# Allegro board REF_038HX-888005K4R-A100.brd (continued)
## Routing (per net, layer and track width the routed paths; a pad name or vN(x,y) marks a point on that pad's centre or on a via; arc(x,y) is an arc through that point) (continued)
D10901: length 268.7
  TOP w0.203: v2(221.27,240.33) 220.98,240.03 220.98,238.29 219.28,236.6 219.28,233.36 214.12,228.2 SITE2.91
  L05_SIGNAL w0.135: 254.73,254.67 254.73,254.08 255.08,253.72 256.42,253.72 258.68,255.99 258.68,309.03 279.04,329.39 279.04,335.94 278.28,336.71 275.56,336.71 274.13,335.27 274.13,334.28
  L05_SIGNAL w0.145: 274.13,334.28 274.49,333.92 276.84,333.92 277.13,333.63 D109.01 ; v2(255.45,254.94) 255,254.94 254.73,254.67
  L22_SIGNAL w0.135: 220.91,240.7 220.91,243.99 221.98,245.06 222.17,245.06 222.35,244.89 222.54,244.89 222.73,245.08 222.73,245.27 222.56,245.45 222.56,245.64 223.76,246.84 224.32,246.84 224.68,246.47 224.68,241.14 225.2,240.62 226.11,240.62 226.69,241.2 226.69,246.32 227.2,246.84 230.93,246.84 231.4,246.37 231.4,236.52 232.05,235.87 233.27,235.87 233.88,236.48 233.88,246.63 234.24,247 235.01,247 235.34,246.66 235.34,236.22 235.87,235.69 237.56,235.69 238.04,236.16 238.04,246.22 238.65,246.84 251.13,246.84 251.68,246.29 251.68,244.05 251.11,243.48 242.16,243.48 241.34,242.66 241.34,239.22 242.07,238.49 260.03,238.49 260.95,239.41 260.95,240.66 254.73,246.88 254.73,254.67
  L22_SIGNAL w0.145: v2(255.45,254.94) 255,254.94 254.73,254.67 ; v2(221.27,240.33) 220.91,240.7
D10902: length 268.7
  TOP w0.203: v2(231.73,227.81) 231.44,228.1 224.66,228.1 219.39,222.83 SITE2.87
  L03_SIGNAL w0.135: 254.73,288.23 254.73,289.31 249.72,294.32 249.72,303.52 273.03,326.84 273.03,328.64
  L03_SIGNAL w0.145: 254.73,288.23 255,287.96 v2(255.45,287.96) ; 273.03,328.64 D109.02
  L22_SIGNAL w0.135: 254.73,287.69 254.73,286.42 254.22,285.91 253.08,285.91 251.91,287.08 251.91,301.72 257.33,307.14 269.91,307.14 272.49,304.56 272.49,294.81 262.47,284.79 262.47,244.51 267.05,239.93 267.05,216.1 266.52,215.56 262.59,215.56 261.97,216.18 261.97,235.46 261.52,235.91 241.64,235.91 233.91,228.17 232.1,228.17
  L22_SIGNAL w0.145: v2(231.73,227.81) 232.1,228.17 ; v2(255.45,287.96) 255,287.96 254.73,287.69
D10903: length 268.7
  TOP w0.203: v2(220.13,240.33) 220.43,240.03 220.43,238.52 218.73,236.83 218.73,233.59 213.72,228.57 SITE2.92
  L05_SIGNAL w0.135: 254.32,254.67 254.32,253.91 254.91,253.32 256.58,253.32 259.09,255.82 259.09,308.86 279.45,329.22 279.45,336.11 278.45,337.12 275.39,337.12 273.72,335.44 273.72,334.41
  L05_SIGNAL w0.145: v2(253.59,254.94) 254.05,254.94 254.32,254.67 ; D109.03 273.72,334.41
  L22_SIGNAL w0.135: 220.5,240.7 220.5,244.16 223.59,247.24 224.49,247.24 225.09,246.64 225.09,241.31 225.37,241.03 225.94,241.03 226.28,241.37 226.28,246.49 227.03,247.24 231.1,247.24 231.8,246.54 231.8,236.69 232.22,236.27 233.1,236.27 233.47,236.65 233.47,246.8 234.07,247.4 235.18,247.4 235.75,246.83 235.75,236.39 236.04,236.1 237.39,236.1 237.63,236.33 237.63,246.39 238.48,247.24 251.3,247.24 252.09,246.45 252.09,243.88 251.28,243.07 242.33,243.07 241.75,242.49 241.75,239.39 242.23,238.9 259.86,238.9 260.54,239.58 260.54,240.49 254.32,246.71 254.32,254.67
  L22_SIGNAL w0.145: v2(253.59,254.94) 254.05,254.94 254.32,254.67 ; v2(220.13,240.33) 220.5,240.7
D10904: length 268.7
  TOP w0.203: v2(231.73,228.95) 231.44,228.65 224.43,228.65 219.01,223.23 SITE2.88
  L03_SIGNAL w0.135: 272.62,328.68 272.62,327.01 249.31,303.69 249.31,294.15 254.32,289.14 254.32,288.23
  L03_SIGNAL w0.145: D109.04 269.31,330.2 269.04,329.93 269.04,329.2 269.21,329.03 272.27,329.03 272.62,328.68 ; 254.32,288.23 254.05,287.96 v2(253.59,287.96)
  L22_SIGNAL w0.135: 232.1,228.58 233.74,228.58 234.99,229.83 234.99,230.02 234.93,230.08 234.93,230.27 235.12,230.46 235.31,230.46 235.37,230.4 235.56,230.4 241.47,236.32 261.69,236.32 262.38,235.63 262.38,216.35 262.76,215.97 266.35,215.97 266.64,216.27 266.64,239.76 262.06,244.34 262.06,284.96 272.08,294.98 272.08,304.4 269.74,306.73 257.5,306.73 252.31,301.55 252.31,287.25 253.25,286.32 254.05,286.32 254.32,286.59 254.32,287.69
  L22_SIGNAL w0.145: v2(231.73,228.95) 232.1,228.58 ; v2(253.59,287.96) 254.05,287.96 254.32,287.69
D10905: length 268.7
  TOP w0.203: SITE2.75 226.04,218.03 226.11,217.96 234.48,217.96 v2(234.78,217.66)
  L05_SIGNAL w0.135: 269.97,265.48 269.97,264.93 269.27,264.23 267.28,264.23 264.55,266.96 264.55,310.56 282.37,328.38 282.37,338.89 281.11,340.14 267.5,340.14 265.34,337.99 265.34,334.37
  L05_SIGNAL w0.145: v2(270.69,265.75) 270.24,265.75 269.97,265.48 ; D109.05 265.34,334.37
  L20_SIGNAL w0.135: 269.97,265.48 269.97,263.55 270.83,262.69 272.56,262.69 272.93,263.06 272.93,275.29 274.4,276.76 283.7,276.76 284.95,275.5 284.95,221.53 281.45,218.03 239.29,218.03 239.16,217.89 239.16,217.62 239.02,217.48 238.75,217.48 238.62,217.62 238.62,217.89 238.48,218.03 238.22,218.03 238.08,217.89 238.08,217.62 237.95,217.48 237.68,217.48 237.54,217.62 237.54,217.89 237.41,218.03 237.14,218.03 237,217.89 237,217.62 236.87,217.48 236.6,217.48 236.47,217.62 236.47,217.89 236.33,218.03 235.15,218.03
  L20_SIGNAL w0.145: v2(270.69,265.75) 270.24,265.75 269.97,265.48 ; v2(234.78,217.66) 235.15,218.03
D10906: length 268.7
  TOP w0.203: v2(215.49,243.07) 215.19,242.77 215.19,238.91 214.32,238.04 214.32,234.11 211.32,231.12 SITE2.98
  L03_SIGNAL w0.135: 254.73,282.53 254.73,283.45 245.97,292.21 245.97,304.79 262.45,321.27 262.45,328.22
  L03_SIGNAL w0.145: v2(255.45,282.26) 255,282.26 254.73,282.53 ; 262.45,328.22 D109.06
  L20_SIGNAL w0.135: 254.73,281.99 254.73,278.49 256.76,276.45 256.76,274.95 255.28,273.47 253.83,273.47 252.13,275.16 252.13,278.94 251.75,279.32 250.49,279.32 250.07,278.9 250.07,274.07 251.76,272.38 251.76,266.35 243.29,257.88 235.32,257.88 234.32,256.88 234.32,253.81 236.32,251.81 238.71,251.81 241.25,249.28 259.82,249.28 260.42,248.69 260.42,246.45 259.95,245.99 246.32,245.99 245.64,245.31 245.64,243.82 246.32,243.14 263.81,243.14 264.53,242.42 264.53,239.46 264.03,238.96 247.09,238.96 241.37,244.68 241.37,246.4 240.72,247.05 237.32,247.05 232.67,251.69 220.68,251.69 216.37,247.38 216.37,247.19 216.54,247.01 216.54,246.82 216.35,246.63 216.16,246.63 215.99,246.81 215.79,246.81 215.12,246.13 215.12,243.43
  L20_SIGNAL w0.145: v2(255.45,282.26) 255,282.26 254.73,281.99 ; v2(215.49,243.07) 215.12,243.43
D10907: length 268.7
  TOP w0.203: v2(234.78,218.8) 234.48,218.5 226.15,218.5 226.08,218.43 SITE2.76
  L05_SIGNAL w0.135: 264.93,334.4 264.93,338.16 267.33,340.55 281.28,340.55 282.78,339.06 282.78,328.21 264.96,310.39 264.96,267.13 267.45,264.64 269.1,264.64 269.56,265.1 269.56,265.48
  L05_SIGNAL w0.145: 269.56,265.48 269.29,265.75 v2(268.83,265.75) ; D109.07 261.52,332.74 261.34,332.92 261.34,333.8 261.68,334.14 264.67,334.14 264.93,334.4
  L20_SIGNAL w0.135: 269.56,265.48 269.56,263.38 270.66,262.28 272.73,262.28 273.34,262.89 273.34,275.12 274.57,276.35 283.53,276.35 284.55,275.33 284.55,221.7 281.28,218.43 235.15,218.43
  L20_SIGNAL w0.145: v2(234.78,218.8) 235.15,218.43 ; 269.56,265.48 269.29,265.75 v2(268.83,265.75)
D10908: length 268.7
  TOP w0.203: v2(214.34,243.07) 214.64,242.77 214.64,239.13 213.77,238.26 213.77,234.34 210.92,231.49 SITE2.99
  L03_SIGNAL w0.135: 254.32,282.53 254.32,283.28 245.57,292.04 245.57,304.96 262.04,321.44 262.04,328.33
  L03_SIGNAL w0.145: 262.04,328.33 261.35,329.03 260.52,329.03 D109.08 ; v2(253.59,282.26) 254.05,282.26 254.32,282.53
  L20_SIGNAL w0.135: 254.32,281.99 254.32,278.32 256.36,276.28 256.36,275.12 255.11,273.88 254,273.88 252.54,275.33 252.54,279.11 251.92,279.73 250.32,279.73 249.66,279.07 249.66,273.9 251.35,272.22 251.35,266.52 243.12,258.29 235.15,258.29 233.91,257.05 233.91,253.64 236.15,251.41 238.54,251.41 241.08,248.87 259.65,248.87 260.01,248.52 260.01,246.62 259.78,246.4 246.15,246.4 245.24,245.48 245.24,243.65 246.15,242.73 263.64,242.73 264.12,242.25 264.12,239.63 263.86,239.37 247.26,239.37 241.78,244.85 241.78,246.57 240.89,247.46 237.49,247.46 232.84,252.1 220.51,252.1 214.71,246.3 214.71,243.43
  L20_SIGNAL w0.145: v2(253.59,282.26) 254.05,282.26 254.32,281.99 ; v2(214.34,243.07) 214.71,243.43
D10909: length 268.7
  TOP w0.203: v2(219.34,243.07) 219.05,242.77 219.05,238.44 217.8,237.19 217.8,233.61 213.32,229.13 SITE2.93
  L05_SIGNAL w0.135: 255.37,334.17 255.37,336.32 251.52,340.17 234.61,340.17 231.41,336.97 231.41,315.42 248.15,298.68 248.15,267.87 251.93,264.09 254.08,264.09 254.73,264.74 254.73,265.48
  L05_SIGNAL w0.145: v2(255.45,265.75) 255,265.75 254.73,265.48 ; D109.09 255.37,334.17
  L20_SIGNAL w0.135: 254.73,265.48 254.73,264.32 256.51,262.54 256.51,256.8 255.91,256.2 253.73,256.2 253.09,256.83 253.09,260.7 252.86,260.93 250.35,260.93 250.07,260.66 250.07,256.09 249.06,255.08 242.56,255.08 241.92,254.43 241.92,253.03 242.51,252.43 259.44,252.43 263.06,248.81 265.3,248.81 266.74,247.37 266.74,236.62 265.87,235.75 243.7,235.75 230.42,249.03 222.86,249.03 220.34,246.51 220.34,246.32 220.51,246.14 220.51,245.95 220.32,245.76 220.13,245.76 219.96,245.94 219.77,245.94 218.98,245.15 218.98,243.43
  L20_SIGNAL w0.145: 254.73,265.48 255,265.75 v2(255.45,265.75) ; v2(219.34,243.07) 218.98,243.43
D10910: length 268.7
  TOP w0.203: SITE2.122 201.72,231.79 200.33,233.17 200.33,240.03 v2(200.63,240.33)
  L03_SIGNAL w0.135: 252.22,328.16 252.22,317.35 225.72,290.84 225.72,285.24 218.63,278.16 213.65,278.16 208.74,273.26 208.74,271.72
  L03_SIGNAL w0.145: 252.22,328.16 D109.10 ; v2(209.47,271.45) 209.01,271.45 208.74,271.72
  L22_SIGNAL w0.135: 208.74,271.18 208.74,270.27 209.14,269.87 209.73,269.87 210.7,270.84 210.7,279.3 216.13,284.73 216.13,314 217.09,314.96 219.2,314.96 220.2,313.96 220.2,303.87 220.59,303.47 221.92,303.47 222.49,304.04 222.49,314.02 223.42,314.96 225.27,314.96 226.17,314.05 226.17,268.72 225.1,267.65 217.05,267.65 211.4,262 211.4,254.09 208.2,250.9 206.65,250.9 200.27,244.51 200.27,242.39 200.4,242.25 200.65,242.25 200.78,242.12 200.78,241.85 200.65,241.71 200.4,241.71 200.27,241.58 200.27,240.7
  L22_SIGNAL w0.145: v2(200.63,240.33) 200.27,240.7 ; v2(209.47,271.45) 209.01,271.45 208.74,271.18
D10911: length 268.7
  TOP w0.203: SITE2.94 212.92,229.51 217.25,233.84 217.25,237.42 218.5,238.66 218.5,242.77 v2(218.2,243.07)
  L05_SIGNAL w0.135: 254.32,265.48 254.32,264.91 253.91,264.5 252.1,264.5 248.55,268.04 248.55,298.85 231.82,315.59 231.82,336.8 234.78,339.76 251.35,339.76 254.97,336.15 254.97,334.26
  L05_SIGNAL w0.145: 254.32,265.48 254.05,265.75 v2(253.59,265.75) ; 254.97,334.26 254.61,333.9 251.36,333.9 251.06,333.6 251.06,332.93 251.25,332.74 D109.11
  L20_SIGNAL w0.135: 218.57,243.43 218.57,245.32 222.69,249.44 230.59,249.44 243.87,236.16 265.7,236.16 266.33,236.79 266.33,247.2 265.13,248.4 262.89,248.4 259.27,252.02 242.34,252.02 241.51,252.86 241.51,254.6 242.39,255.49 248.89,255.49 249.67,256.26 249.67,260.82 250.18,261.34 253.03,261.34 253.5,260.87 253.5,257 253.9,256.61 255.74,256.61 256.1,256.97 256.1,262.37 254.32,264.15 254.32,265.48
  L20_SIGNAL w0.145: v2(218.2,243.07) 218.57,243.43 ; 254.32,265.48 254.05,265.75 v2(253.59,265.75)
D10912: length 268.7
  TOP w0.203: v2(199.49,240.33) 199.79,240.03 199.79,232.94 201.32,231.41 SITE2.123
  L03_SIGNAL w0.135: 251.82,328.28 251.82,317.52 225.31,291.01 225.31,285.41 218.46,278.57 213.48,278.57 208.33,273.43 208.33,271.72
  L03_SIGNAL w0.145: 208.33,271.72 208.07,271.45 v2(207.61,271.45) ; D109.12 250.36,329.03 251.07,329.03 251.82,328.28
  L22_SIGNAL w0.135: 208.33,271.18 208.33,270.1 208.97,269.46 209.9,269.46 211.11,270.67 211.11,279.13 216.54,284.56 216.54,313.83 217.26,314.55 219.03,314.55 219.79,313.79 219.79,303.7 220.42,303.06 222.09,303.06 222.89,303.87 222.89,313.85 223.59,314.55 225.1,314.55 225.76,313.88 225.76,268.89 224.93,268.06 216.88,268.06 210.99,262.17 210.99,254.26 208.03,251.31 206.48,251.31 199.86,244.68 199.86,240.7
  L22_SIGNAL w0.145: v2(207.61,271.45) 208.07,271.45 208.33,271.18 ; v2(199.49,240.33) 199.86,240.7
D10913: length 268.7
  TOP w0.203: SITE2.95 212.52,229.94 216.33,233.75 216.33,238.1 217.12,238.88 217.12,240.03 v2(217.41,240.33)
  L05_SIGNAL w0.135: 244.95,334.44 244.95,336.07 243.73,337.29 235.46,337.29 233.96,335.8 233.96,318.85 251.96,300.86 251.96,271.08 253,270.04 254.22,270.04 254.73,270.55 254.73,271.18
  L05_SIGNAL w0.145: 254.73,271.18 255,271.45 v2(255.45,271.45) ; D109.13 244.95,334.44
  L22_SIGNAL w0.135: 217.05,240.7 217.05,241.61 217.18,241.75 217.43,241.75 217.56,241.88 217.56,242.15 217.43,242.29 217.18,242.29 217.05,242.42 217.05,244.07 221.99,249.01 249.21,249.01 251.15,250.96 251.15,255.65 259.71,264.21 259.71,286.27 267.69,294.25 267.69,303.6 267.04,304.25 265.55,304.25 264.97,303.68 264.97,299.02 264.64,298.69 262.94,298.69 262.55,299.08 262.55,303.12 261.23,304.44 258.74,304.44 256.8,302.5 256.8,270.26 256.42,269.87 255.01,269.87 254.73,270.15 254.73,271.18
  L22_SIGNAL w0.145: v2(255.45,271.45) 255,271.45 254.73,271.18 ; v2(217.41,240.33) 217.05,240.7
D10914: length 268.7
  TOP w0.203: SITE2.124 200.92,230.78 198.41,233.29 198.41,242.77 v2(198.7,243.07)
  L03_SIGNAL w0.135: 242.05,328.14 242.05,317.84 219.94,295.73 219.94,290.01 215.19,285.27 210.84,285.27 208.74,283.17 208.74,282.53
  L03_SIGNAL w0.145: v2(209.47,282.26) 209.01,282.26 208.74,282.53 ; 242.05,328.14 D109.14
  L20_SIGNAL w0.135: 208.74,281.99 208.74,281.45 209.05,281.14 209.83,281.14 210.71,282.02 210.71,294.69 214.06,298.04 214.06,315.32 215.27,316.53 221.89,316.53 223.41,315.01 223.41,303.5 224.41,302.5 228.88,302.5 229.72,303.34 229.72,313.05 231.67,315 237.55,315 238.92,313.63 238.92,297.31 236.48,294.86 229.86,294.86 226.53,291.53 226.53,282.6 225.17,281.24 221.2,281.24 219.45,279.49 219.45,266.82 218.19,265.56 213.79,265.56 202.91,254.68 202.91,252.91 198.34,248.34 198.34,245.43 198.47,245.3 198.72,245.3 198.85,245.16 198.85,244.89 198.72,244.76 198.47,244.76 198.34,244.63 198.34,243.43
  L20_SIGNAL w0.145: v2(198.7,243.07) 198.34,243.43 ; v2(209.47,282.26) 209.01,282.26 208.74,281.99
D10915: length 268.7
  TOP w0.203: SITE2.96 212.12,230.31 215.79,233.98 215.79,238.32 216.57,239.11 216.57,240.03 v2(216.27,240.33)
  L05_SIGNAL w0.135: 254.32,271.18 254.32,270.72 254.05,270.45 253.17,270.45 252.36,271.25 252.36,301.03 234.37,319.02 234.37,335.63 235.63,336.89 243.56,336.89 244.54,335.9 244.54,334.43
  L05_SIGNAL w0.145: 254.32,271.18 254.05,271.45 v2(253.59,271.45) ; 244.54,334.43 244,333.89 240.9,333.89 240.66,333.65 240.66,332.98 240.9,332.74 D109.15
  L22_SIGNAL w0.135: 254.32,271.18 254.32,269.98 254.84,269.46 256.58,269.46 257.21,270.09 257.21,302.33 258.91,304.03 261.07,304.03 262.14,302.95 262.14,298.91 262.77,298.28 264.81,298.28 265.38,298.85 265.38,303.51 265.72,303.85 266.87,303.85 267.28,303.43 267.28,294.42 259.3,286.44 259.3,264.38 250.74,255.82 250.74,251.13 249.04,249.42 221.82,249.42 216.64,244.24 216.64,240.7
  L22_SIGNAL w0.145: 254.32,271.18 254.05,271.45 v2(253.59,271.45) ; v2(216.27,240.33) 216.64,240.7
D10916: length 268.7
  TOP w0.203: v2(197.56,243.07) 197.86,242.77 197.86,233.06 200.52,230.4 SITE2.125
  L03_SIGNAL w0.135: 241.64,328.32 241.64,318.01 219.53,295.9 219.53,290.18 215.02,285.67 210.67,285.67 208.33,283.34 208.33,282.53
  L03_SIGNAL w0.145: D109.16 240.2,329.03 240.93,329.03 241.64,328.32 ; v2(207.61,282.26) 208.07,282.26 208.33,282.53
  L20_SIGNAL w0.135: 208.33,281.99 208.33,281.28 208.88,280.74 210,280.74 211.12,281.85 211.12,294.52 214.47,297.87 214.47,315.15 215.44,316.12 221.72,316.12 223,314.84 223,303.33 224.25,302.09 229.05,302.09 230.13,303.17 230.13,312.88 231.84,314.59 237.38,314.59 238.51,313.46 238.51,297.48 236.31,295.27 229.69,295.27 226.12,291.7 226.12,282.77 225,281.65 221.03,281.65 219.04,279.66 219.04,266.99 218.02,265.97 213.62,265.97 202.5,254.85 202.5,253.08 197.93,248.51 197.93,243.43
  L20_SIGNAL w0.145: v2(197.56,243.07) 197.93,243.43 ; v2(207.61,282.26) 208.07,282.26 208.33,281.99
D11001: length 268.7
  TOP w0.203: v2(231.73,220.09) 231.44,220.39 226.26,220.39 225.5,219.63 SITE2.79
  L05_SIGNAL w0.135: 275.66,354.53 275.66,357.21 276.41,357.96 284.24,357.96 285.8,356.4 285.8,327.89 267.2,309.29 267.2,270.99 268.35,269.84 269.46,269.84 269.97,270.35 269.97,271.18
  L05_SIGNAL w0.145: v2(270.69,271.45) 270.24,271.45 269.97,271.18 ; D110.01 275.66,354.53
  L22_SIGNAL w0.135: 269.97,271.18 269.97,268.62 272.29,266.3 272.29,263.11 267.67,258.49 267.67,247.9 274.57,241 274.57,211.38 273.65,210.46 255.32,210.46 254.43,211.34 254.43,226.75 253.86,227.31 251.12,227.31 250.38,226.57 250.38,221.73 249.49,220.84 247.07,220.84 246.31,221.6 246.31,225.36 245.62,226.05 242.4,226.05 236.8,220.46 234.92,220.46 234.79,220.32 234.79,219.85 234.65,219.72 234.38,219.72 234.25,219.85 234.25,220.32 234.12,220.46 233.85,220.46 233.71,220.32 233.71,219.85 233.58,219.72 233.31,219.72 233.17,219.85 233.17,220.32 233.04,220.46 232.1,220.46
  L22_SIGNAL w0.145: v2(231.73,220.09) 232.1,220.46 ; 269.97,271.18 270.24,271.45 v2(270.69,271.45)
D11002: length 268.7
  TOP w0.203: SITE2.116 204.12,238.74 204.19,238.82 204.19,240.03 v2(204.49,240.33)
  L03_SIGNAL w0.135: 208.74,288.23 208.74,293.02 232.79,317.07 232.79,334.29 236.03,337.53 267.35,337.53 272.59,342.77 272.59,348.52
  L03_SIGNAL w0.145: v2(209.47,287.96) 209.01,287.96 208.74,288.23 ; 272.59,348.52 D110.02
  L22_SIGNAL w0.135: 208.74,287.69 208.74,286.19 209.3,285.63 211.69,285.63 212.5,286.44 212.5,314.76 214.86,317.12 227.64,317.12 229.35,315.42 229.35,265.45 227.37,263.48 217.65,263.48 214.21,260.04 214.21,254.24 204.12,244.15 204.12,242.51 204.26,242.38 204.51,242.38 204.64,242.25 204.64,241.98 204.51,241.84 204.26,241.84 204.12,241.71 204.12,240.7
  L22_SIGNAL w0.145: v2(204.49,240.33) 204.12,240.7 ; 208.74,287.69 209.01,287.96 v2(209.47,287.96)
D11003: length 268.7
  TOP w0.203: v2(231.73,221.23) 231.44,220.94 226.03,220.94 225.12,220.03 SITE2.80
  L05_SIGNAL w0.135: 275.25,354.49 275.25,357.38 276.24,358.37 284.41,358.37 286.21,356.57 286.21,327.72 267.6,309.12 267.6,271.16 268.52,270.25 269.29,270.25 269.56,270.52 269.56,271.18
  L05_SIGNAL w0.145: D110.03 271.85,353.06 271.59,353.33 271.59,353.77 272.01,354.19 274.95,354.19 275.25,354.49 ; 269.56,271.18 269.29,271.45 v2(268.83,271.45)
  L22_SIGNAL w0.135: 232.1,220.87 236.63,220.87 242.23,226.46 245.79,226.46 246.72,225.53 246.72,221.77 247.24,221.25 249.32,221.25 249.97,221.9 249.97,226.74 250.95,227.72 254.03,227.72 254.84,226.92 254.84,211.51 255.49,210.87 273.48,210.87 274.16,211.55 274.16,240.83 267.38,247.61 267.26,247.73 267.26,258.66 271.88,263.28 271.88,266.13 269.56,268.45 269.56,271.18
  L22_SIGNAL w0.145: v2(231.73,221.23) 232.1,220.87 ; 269.56,271.18 269.29,271.45 v2(268.83,271.45)
D11004: length 268.7
  TOP w0.203: v2(203.35,240.33) 203.65,240.03 203.65,238.81 203.72,238.74 SITE2.117
  L03_SIGNAL w0.135: 208.33,288.23 208.33,293.19 232.38,317.24 232.38,334.46 235.86,337.94 267.18,337.94 272.18,342.94 272.18,348.61
  L03_SIGNAL w0.145: D110.04 270.68,349.35 271.44,349.35 272.18,348.61 ; 208.33,288.23 208.07,287.96 v2(207.61,287.96)
  L22_SIGNAL w0.135: 208.33,287.69 208.33,286.02 209.13,285.22 211.86,285.22 212.9,286.27 212.9,314.59 215.03,316.72 227.47,316.72 228.94,315.25 228.94,265.62 227.2,263.89 217.48,263.89 213.8,260.21 213.8,254.41 203.71,244.32 203.71,240.7
  L22_SIGNAL w0.145: v2(207.61,287.96) 208.07,287.96 208.33,287.69 ; v2(203.35,240.33) 203.71,240.7
D11005: length 268.7
  TOP w0.203: v2(231.73,215.73) 231.44,216.03 225.58,216.03 224.38,217.23 SITE2.73
  L05_SIGNAL w0.135: 269.97,254.67 269.97,254.29 270.24,254.02 271.79,254.02 273.17,255.4 273.17,310.7 288.65,326.17 288.65,357.77 285.34,361.07 268.71,361.07 264.71,357.07 264.71,355.32
  L05_SIGNAL w0.145: D110.05 264.71,355.32 ; 269.97,254.67 270.24,254.94 v2(270.69,254.94)
  L22_SIGNAL w0.135: 232.1,216.1 234.02,216.1 234.15,215.96 234.15,215.69 234.29,215.55 234.56,215.55 234.69,215.69 234.69,215.96 234.82,216.1 235.09,216.1 235.23,215.96 235.23,215.69 235.36,215.55 235.63,215.55 235.77,215.69 235.77,215.96 235.9,216.1 236.17,216.1 236.31,215.96 236.31,215.69 236.44,215.55 236.71,215.55 236.84,215.69 236.84,215.96 236.98,216.1 247.1,216.1 249.23,213.97 249.23,208.13 251.42,205.94 276.18,205.94 278.23,207.99 278.23,243.28 269.97,251.54 269.97,254.67
  L22_SIGNAL w0.145: 269.97,254.67 270.24,254.94 v2(270.69,254.94) ; v2(231.73,215.73) 232.1,216.1
D11006: length 268.7
  TOP w0.203: v2(202.56,243.07) 202.26,242.77 202.26,233.08 202.52,232.83 SITE2.120
  L03_SIGNAL w0.135: 262.38,348.47 262.38,343.42 259.12,340.16 234.95,340.16 230.17,335.38 230.17,322.23 208.74,300.8 208.74,299.04
  L03_SIGNAL w0.145: 262.38,348.47 D110.06 ; v2(209.47,298.77) 209.01,298.77 208.74,299.04
  L20_SIGNAL w0.135: 208.74,298.5 208.74,297.54 209.07,297.21 210.15,297.21 210.98,298.05 210.98,319.18 212.93,321.13 238.07,321.13 241.64,317.55 241.64,294.02 239.93,292.31 230.96,292.31 229.09,290.44 229.09,280.17 227.55,278.62 222.63,278.62 221.56,277.55 221.56,264.4 219.31,262.14 213.21,262.14 206.28,255.21 206.28,251.77 202.19,247.68 202.19,245.32 202.33,245.19 202.58,245.19 202.71,245.06 202.71,244.79 202.58,244.65 202.33,244.65 202.19,244.52 202.19,243.43
  L20_SIGNAL w0.145: 208.74,298.5 209.01,298.77 v2(209.47,298.77) ; v2(202.56,243.07) 202.19,243.43
D11007: length 268.7
  TOP w0.203: SITE2.74 224.75,217.63 225.81,216.58 231.44,216.58 v2(231.73,216.87)
  L05_SIGNAL w0.135: 269.56,254.67 269.56,254.12 270.07,253.61 271.96,253.61 273.58,255.23 273.58,310.53 289.05,326 289.05,357.94 285.51,361.48 268.54,361.48 264.3,357.24 264.3,354.98
  L05_SIGNAL w0.145: D110.07 263.24,354.41 263.74,354.41 264.3,354.98 ; 269.56,254.67 269.29,254.94 v2(268.83,254.94)
  L22_SIGNAL w0.135: 269.56,254.67 269.56,251.37 277.82,243.11 277.82,208.16 276.01,206.35 251.59,206.35 249.63,208.3 249.63,214.14 247.27,216.51 232.1,216.51
  L22_SIGNAL w0.145: v2(268.83,254.94) 269.29,254.94 269.56,254.67 ; v2(231.73,216.87) 232.1,216.51
D11008: length 268.7
  TOP w0.203: SITE2.121 202.12,232.45 201.72,232.85 201.72,242.77 v2(201.42,243.07)
  L03_SIGNAL w0.135: 208.33,299.04 208.33,300.97 229.76,322.4 229.76,335.55 234.78,340.57 258.95,340.57 261.98,343.59 261.98,348.6
  L03_SIGNAL w0.145: v2(207.61,298.77) 208.07,298.77 208.33,299.04 ; 261.98,348.6 261.23,349.35 260.52,349.35 D110.08
  L20_SIGNAL w0.135: 208.33,298.5 208.33,297.37 208.9,296.8 210.32,296.8 211.39,297.88 211.39,319.01 213.1,320.72 237.9,320.72 241.23,317.38 241.23,294.19 239.76,292.72 230.79,292.72 228.69,290.61 228.69,280.33 227.38,279.03 222.46,279.03 221.15,277.72 221.15,264.57 219.14,262.55 213.04,262.55 205.87,255.38 205.87,251.94 201.79,247.85 201.79,243.43
  L20_SIGNAL w0.145: v2(201.42,243.07) 201.79,243.43 ; 208.33,298.5 208.07,298.77 v2(207.61,298.77)
D11009: length 268.7
  TOP w0.203: v2(213.56,240.33) 213.26,240.03 213.26,239.19 213.01,238.95 213.01,234.29 210.52,231.79 SITE2.100
  L05_SIGNAL w0.135: 239.49,254.67 239.49,253.71 238.98,253.2 236.73,253.2 235.52,254.42 235.52,258.13 232.91,260.74 232.91,274.73 227.6,280.03 227.6,288.93 228.87,290.19 228.87,299.08 226.11,301.85 226.11,355.23 232.2,361.32 252.15,361.32 255.18,358.29 255.18,354.69
  L05_SIGNAL w0.145: v2(240.21,254.94) 239.76,254.94 239.49,254.67 ; D110.09 255.18,354.69
  L22_SIGNAL w0.135: 213.19,240.7 213.19,241.78 213.32,241.92 213.57,241.92 213.71,242.05 213.71,242.32 213.57,242.46 213.32,242.46 213.19,242.59 213.19,244.09 220.3,251.2 246.26,251.2 247.28,252.23 247.28,259.53 249.25,261.5 249.25,276.95 247.9,278.3 244.4,278.3 242.78,276.67 242.78,254.83 241.88,253.93 239.77,253.93 239.49,254.21 239.49,254.67
  L22_SIGNAL w0.145: 239.49,254.67 239.76,254.94 v2(240.21,254.94) ; v2(213.56,240.33) 213.19,240.7
D11010: length 268.7
  TOP w0.203: SITE2.135 192.51,222.43 187.88,227.05 180.84,227.05 v2(180.55,227.35)
  L03_SIGNAL w0.135: 193.5,271.72 193.5,276.16 204,286.66 204,299.59 227.63,323.22 227.63,336.43 233.89,342.69 249.73,342.69 252.29,345.26 252.29,348.54
  L03_SIGNAL w0.145: 252.29,348.54 D110.10 ; v2(194.23,271.45) 193.77,271.45 193.5,271.72
  L22_SIGNAL w0.135: 193.5,271.18 193.5,270.41 194.13,269.79 196.43,269.79 198.04,271.41 198.04,303.52 199.12,304.6 202.68,304.6 203.87,303.41 203.87,272.73 196.46,265.33 196.46,254.12 190.23,247.88 190.23,246.49 189.46,245.73 187.18,245.73 186.56,245.11 186.56,240.62 185.88,239.94 184.05,239.94 178.68,234.57 178.68,230.9 178.81,230.77 179.05,230.77 179.18,230.64 179.18,230.37 179.05,230.23 178.81,230.23 178.68,230.1 178.68,229.83 178.81,229.69 179.05,229.69 179.18,229.56 179.18,229.29 179.05,229.15 178.81,229.15 178.68,229.02 178.68,227.57 179.26,226.98 180.18,226.98
  L22_SIGNAL w0.145: v2(194.23,271.45) 193.77,271.45 193.5,271.18 ; 180.18,226.98 v2(180.55,227.35)
D11011: length 268.7
  TOP w0.203: v2(212.41,240.33) 212.71,240.03 212.71,239.42 212.46,239.18 212.46,234.51 210.12,232.17 SITE2.101
  L05_SIGNAL w0.135: 254.77,354.84 254.77,358.12 251.98,360.91 232.37,360.91 226.52,355.06 226.52,302.02 229.28,299.25 229.28,290.03 228.01,288.76 228.01,280.2 233.31,274.9 233.31,260.91 235.92,258.3 235.92,254.59 236.9,253.61 238.81,253.61 239.08,253.88 239.08,254.67
  L05_SIGNAL w0.145: 239.08,254.67 238.81,254.94 v2(238.35,254.94) ; D110.11 251.19,353.06 250.86,353.39 250.86,354.12 251.16,354.41 254.35,354.41 254.77,354.84
  L22_SIGNAL w0.135: 239.08,254.67 239.08,254.04 239.6,253.52 242.05,253.52 243.18,254.66 243.18,276.5 244.57,277.89 247.73,277.89 248.84,276.78 248.84,261.66 246.87,259.7 246.87,252.4 246.09,251.61 220.13,251.61 212.78,244.26 212.78,240.7
  L22_SIGNAL w0.145: v2(238.35,254.94) 238.81,254.94 239.08,254.67 ; v2(212.41,240.33) 212.78,240.7
D11012: length 268.7
  TOP w0.203: SITE2.136 192.13,222.03 187.66,226.5 180.84,226.5 v2(180.55,226.21)
  L03_SIGNAL w0.135: 251.88,348.65 251.88,345.43 249.56,343.1 233.73,343.1 227.22,336.6 227.22,323.39 203.59,299.76 203.59,286.83 193.09,276.33 193.09,271.72
  L03_SIGNAL w0.145: D110.12 250.36,349.35 251.19,349.35 251.88,348.65 ; 193.09,271.72 192.83,271.45 v2(192.37,271.45)
  L22_SIGNAL w0.135: 193.09,271.18 193.09,270.24 193.96,269.38 196.6,269.38 198.45,271.24 198.45,303.35 199.29,304.19 202.51,304.19 203.46,303.24 203.46,272.9 196.05,265.5 196.05,254.29 189.82,248.05 189.82,246.66 189.29,246.14 187.01,246.14 186.15,245.28 186.15,240.78 185.71,240.35 183.88,240.35 178.27,234.74 178.27,227.4 179.09,226.57 180.18,226.57
  L22_SIGNAL w0.145: 180.18,226.57 v2(180.55,226.21) ; 193.09,271.18 192.83,271.45 v2(192.37,271.45)
D11013: length 268.7
  TOP w0.203: SITE2.102 209.72,232.44 211.33,234.05 211.33,242.77 v2(211.63,243.07)
  L05_SIGNAL w0.135: 239.49,265.48 239.49,264.64 239.81,264.31 241.44,264.31 244.34,267.22 244.34,296.72 228.93,312.14 228.93,354.06 233.37,358.5 242.6,358.5 244.67,356.44 244.67,355.04
  L05_SIGNAL w0.145: 239.49,265.48 239.76,265.75 v2(240.21,265.75) ; D110.13 244.67,355.04
  L20_SIGNAL w0.135: 211.26,243.43 211.26,244.47 211.39,244.6 211.64,244.6 211.78,244.74 211.78,245.01 211.64,245.14 211.39,245.14 211.26,245.28 211.26,246.2 221.21,256.15 225.55,256.15 229.92,260.53 240.83,260.53 247.78,267.47 247.78,300.39 246.98,301.19 244.88,301.19 243.95,300.26 243.95,267.2 241.19,264.44 239.62,264.44 239.49,264.58 239.49,265.48
  L20_SIGNAL w0.145: v2(211.63,243.07) 211.26,243.43 ; 239.49,265.48 239.76,265.75 v2(240.21,265.75)
D11014: length 268.7
  TOP w0.203: SITE2.137 191.44,221.63 187.95,225.12 177.55,225.12 v2(177.25,225.42)
  L03_SIGNAL w0.135: 193.5,282.53 193.5,284.05 194.96,285.51 198.17,285.51 201.49,288.83 201.49,300.93 225.28,324.72 225.28,337.4 232.92,345.04 240.48,345.04 242.18,346.74 242.18,348.59
  L03_SIGNAL w0.145: 193.5,282.53 193.77,282.26 v2(194.23,282.26) ; 242.18,348.59 D110.14
  L20_SIGNAL w0.135: 193.5,281.99 193.5,276.07 194.09,275.48 195.87,275.48 196.39,276.01 196.39,291.08 197.72,292.41 200.27,292.41 202.05,290.63 202.05,277.54 197.23,272.72 192.02,272.72 180.48,261.18 180.48,259.86 181.05,259.29 182.12,259.29 192.32,269.49 195.32,269.49 196.29,268.52 196.29,264.92 180.64,249.26 180.64,240.89 173.36,233.61 173.36,228.57 173.49,228.43 173.73,228.43 173.86,228.3 173.86,228.03 173.73,227.89 173.49,227.89 173.36,227.76 173.36,227.49 173.49,227.36 173.73,227.36 173.86,227.22 173.86,226.95 173.73,226.82 173.49,226.82 173.36,226.68 173.36,225.93 174.24,225.05 176.88,225.05
  L20_SIGNAL w0.145: v2(177.25,225.42) 176.88,225.05 ; v2(194.23,282.26) 193.77,282.26 193.5,281.99
D11015: length 268.7
  TOP w0.203: v2(210.48,243.07) 210.78,242.77 210.78,234.27 209.32,232.81 SITE2.103
  L05_SIGNAL w0.135: 239.08,265.48 239.08,264.47 239.64,263.9 241.61,263.9 244.75,267.05 244.75,296.89 229.34,312.31 229.34,353.89 233.54,358.09 242.43,358.09 244.26,356.27 244.26,354.92
  L05_SIGNAL w0.145: 244.26,354.92 243.59,354.25 242.76,354.25 D110.15 ; v2(238.35,265.75) 238.81,265.75 239.08,265.48
  L20_SIGNAL w0.135: 239.08,265.48 239.08,264.41 239.45,264.03 241.36,264.03 244.36,267.03 244.36,300.09 245.05,300.78 246.81,300.78 247.37,300.22 247.37,267.64 240.66,260.94 229.75,260.94 225.38,256.56 221.04,256.56 210.85,246.37 210.85,243.43
  L20_SIGNAL w0.145: v2(238.35,265.75) 238.81,265.75 239.08,265.48 ; v2(210.48,243.07) 210.85,243.43
D11016: length 268.7
  TOP w0.203: v2(177.25,224.28) 177.55,224.57 187.72,224.57 191.06,221.23 SITE2.138
  L03_SIGNAL w0.135: 193.09,282.53 193.09,284.22 194.79,285.92 198,285.92 201.08,289 201.08,301.1 224.87,324.89 224.87,337.57 232.75,345.45 240.31,345.45 241.77,346.91 241.77,348.53
  L03_SIGNAL w0.145: 241.77,348.53 240.95,349.35 240.2,349.35 D110.16 ; v2(192.37,282.26) 192.83,282.26 193.09,282.53
  L20_SIGNAL w0.135: 193.09,281.99 193.09,275.9 193.92,275.07 196.04,275.07 196.8,275.84 196.8,290.91 197.89,292 200.11,292 201.65,290.46 201.65,277.71 197.06,273.13 191.85,273.13 180.07,261.35 180.07,259.69 180.88,258.88 182.29,258.88 192.49,269.08 195.15,269.08 195.88,268.35 195.88,265.09 180.23,249.43 180.23,241.05 172.95,233.78 172.95,225.76 174.07,224.64 176.88,224.64
  L20_SIGNAL w0.145: 193.09,281.99 192.83,282.26 v2(192.37,282.26) ; v2(177.25,224.28) 176.88,224.64
D11101: length 268.7
  TOP w0.203: SITE2.129 198.92,228.97 194.55,233.34 194.55,242.77 v2(194.84,243.07)
  L05_SIGNAL w0.135: 275.62,374.89 275.62,381.23 271.06,385.79 232.01,385.79 225.63,379.4 225.63,370.02 215.92,360.31 215.92,315.27 203.29,302.63 203.29,283.44 206.01,280.73 206.01,265.55 207.17,264.39 208.47,264.39 209.01,264.93 209.01,265.48
  L05_SIGNAL w0.145: v2(209.73,265.75) 209.28,265.75 209.01,265.48 ; D111.01 275.62,374.89
  L20_SIGNAL w0.135: 194.48,243.43 194.48,245.1 194.61,245.23 194.86,245.23 195,245.37 195,245.64 194.86,245.77 194.61,245.77 194.48,245.9 194.48,249.64 198.65,253.81 198.65,258.64 203.97,263.96 203.97,267.37 205.99,269.39 205.99,272.08 207.32,273.41 210.37,273.41 211.68,272.09 211.68,269.43 210.33,268.08 207.71,268.08 206.11,266.48 206.11,264.74 206.76,264.1 208.18,264.1 209.01,264.93 209.01,265.48
  L20_SIGNAL w0.145: 209.01,265.48 209.28,265.75 v2(209.73,265.75) ; v2(194.84,243.07) 194.48,243.43
D11102: length 268.7
  TOP w0.203: SITE2.81 224.27,220.43 226.16,222.32 234.48,222.32 v2(234.78,222.02)
  L03_SIGNAL w0.135: 272.99,369.24 272.99,367.47 273.76,366.7 282.8,366.7 289.05,360.44 289.05,326 280.24,317.19 280.24,296.83 274.42,291.02 274.42,288.18 269.97,283.72 269.97,282.53
  L03_SIGNAL w0.145: v2(270.69,282.26) 270.24,282.26 269.97,282.53 ; 272.99,369.24 D111.02
  L20_SIGNAL w0.135: 235.15,222.39 236.54,222.39 236.68,222.25 236.68,221.98 236.81,221.84 237.08,221.84 237.22,221.98 237.22,222.25 237.35,222.39 237.62,222.39 237.76,222.25 237.76,221.98 237.89,221.84 238.16,221.84 238.29,221.98 238.29,222.25 238.43,222.39 238.7,222.39 238.83,222.25 238.83,221.98 238.97,221.84 239.24,221.84 239.37,221.98 239.37,222.25 239.51,222.39 279.85,222.39 282.28,224.82 282.28,269.02 281.09,270.21 278.69,270.21 277.51,269.03 277.51,262.73 274.61,259.83 270.1,259.83 267.24,262.68 267.24,274.82 269.97,277.55 269.97,281.99
  L20_SIGNAL w0.145: v2(270.69,282.26) 270.24,282.26 269.97,281.99 ; v2(234.78,222.02) 235.15,222.39
D11103: length 268.7
  TOP w0.203: SITE2.130 198.52,228.6 194,233.12 194,242.77 v2(193.7,243.07)
  L05_SIGNAL w0.135: 275.21,375.08 275.21,381.06 270.89,385.38 232.18,385.38 226.04,379.24 226.04,369.85 216.33,360.14 216.33,315.1 203.7,302.46 203.7,283.61 206.42,280.9 206.42,265.72 207.34,264.8 208.3,264.8 208.6,265.1 208.6,265.48
  L05_SIGNAL w0.145: v2(207.87,265.75) 208.33,265.75 208.6,265.48 ; D111.03 271.57,373.38 271.32,373.62 271.32,374.26 271.74,374.67 274.81,374.67 275.21,375.08
  L20_SIGNAL w0.135: 208.6,265.48 208.6,265.1 208.01,264.51 206.93,264.51 206.52,264.91 206.52,266.31 207.88,267.67 210.5,267.67 212.09,269.26 212.09,272.26 210.54,273.82 207.15,273.82 205.59,272.25 205.59,269.56 203.56,267.54 203.56,264.13 198.24,258.81 198.24,253.98 194.07,249.81 194.07,243.43
  L20_SIGNAL w0.145: 208.6,265.48 208.33,265.75 v2(207.87,265.75) ; v2(193.7,243.07) 194.07,243.43
D11104: length 268.7
  TOP w0.203: SITE2.82 223.9,220.83 225.93,222.87 234.48,222.87 v2(234.78,223.16)
  L03_SIGNAL w0.135: 272.58,369.25 272.58,367.3 273.59,366.29 282.63,366.29 288.65,360.27 288.65,326.17 279.83,317.36 279.83,297 274.01,291.19 274.01,288.35 269.56,283.89 269.56,282.53
  L03_SIGNAL w0.145: 269.56,282.53 269.29,282.26 v2(268.83,282.26) ; 272.58,369.25 272.27,369.56 269.31,369.56 268.93,369.94 268.93,370.47 269.31,370.84 D111.04
  L20_SIGNAL w0.135: 235.15,222.8 279.68,222.8 281.87,224.99 281.87,268.85 280.92,269.8 278.86,269.8 277.92,268.87 277.92,262.56 274.78,259.42 269.93,259.42 266.84,262.52 266.84,274.99 269.56,277.71 269.56,281.99
  L20_SIGNAL w0.145: v2(268.83,282.26) 269.29,282.26 269.56,281.99 ; v2(234.78,223.16) 235.15,222.8
D11105: length 268.7
  TOP w0.203: SITE2.126 200.12,229.62 196.48,233.26 196.48,240.03 v2(196.77,240.33)
  L05_SIGNAL w0.135: 209.01,254.67 209.01,254.29 209.46,253.84 210.53,253.84 212.59,255.9 212.59,307.21 218.27,312.89 218.27,359.34 227.98,369.05 227.98,378.43 232.99,383.44 261.89,383.44 264.95,380.38 264.95,375.4
  L05_SIGNAL w0.145: 209.01,254.67 209.28,254.94 v2(209.73,254.94) ; D111.05 264.95,375.4
  L22_SIGNAL w0.135: 196.41,240.7 196.41,241.89 196.54,242.02 196.79,242.02 196.92,242.16 196.92,242.43 196.79,242.56 196.54,242.56 196.41,242.69 196.41,246.21 204.23,254.02 204.23,263.84 207.72,267.34 211.22,267.34 215.36,271.48 215.89,271.48 216.47,270.9 216.47,270.62 208.33,262.49 208.33,258.42 205.97,256.06 205.97,253.6 206.47,253.09 207.98,253.09 209.01,254.12 209.01,254.67
  L22_SIGNAL w0.145: v2(209.73,254.94) 209.28,254.94 209.01,254.67 ; v2(196.77,240.33) 196.41,240.7
D11106: length 268.7
  TOP w0.203: v2(231.73,223.95) 231.44,224.25 225.8,224.25 222.78,221.23 SITE2.83
  L03_SIGNAL w0.135: 262.83,369.24 262.83,364.86 264.01,363.67 281.79,363.67 286.21,359.26 286.21,327.72 273.36,314.87 273.36,295.78 269.97,292.39 269.97,288.23
  L03_SIGNAL w0.145: 269.97,288.23 270.24,287.96 v2(270.69,287.96) ; 262.83,369.24 D111.06
  L22_SIGNAL w0.135: 232.1,224.32 236.11,224.32 238.25,226.45 238.44,226.45 238.77,226.12 238.96,226.12 239.15,226.31 239.15,226.5 238.82,226.83 238.82,227.02 239.01,227.21 239.2,227.21 239.53,226.88 239.72,226.88 239.91,227.07 239.91,227.26 239.58,227.59 239.58,227.78 244.24,232.44 258.23,232.44 259.1,231.56 259.1,214.05 260.05,213.1 269.44,213.1 270.69,214.35 270.69,240.7 264.63,246.76 264.63,272 267.44,274.81 267.44,283.57 269.97,286.09 269.97,287.69
  L22_SIGNAL w0.145: 269.97,287.69 270.24,287.96 v2(270.69,287.96) ; v2(231.73,223.95) 232.1,224.32
D11107: length 268.7
  TOP w0.203: SITE2.127 199.72,229.25 195.93,233.04 195.93,240.03 v2(195.63,240.33)
  L05_SIGNAL w0.135: 264.54,375.36 264.54,380.21 261.72,383.03 233.16,383.03 228.39,378.26 228.39,368.88 218.68,359.17 218.68,312.72 212.99,307.04 212.99,255.73 210.7,253.43 209.29,253.43 208.6,254.12 208.6,254.67
  L05_SIGNAL w0.145: D111.07 263.11,374.6 263.79,374.6 264.54,375.36 ; 208.6,254.67 208.33,254.94 v2(207.87,254.94)
  L22_SIGNAL w0.135: 196,240.7 196,246.38 203.82,254.19 203.82,264.01 207.55,267.75 211.05,267.75 215.19,271.89 216.06,271.89 216.88,271.07 216.88,270.45 208.74,262.32 208.74,258.25 206.37,255.89 206.37,253.77 206.64,253.5 207.81,253.5 208.6,254.29 208.6,254.67
  L22_SIGNAL w0.145: v2(207.87,254.94) 208.33,254.94 208.6,254.67 ; v2(195.63,240.33) 196,240.7
D11108: length 268.7
  TOP w0.203: SITE2.84 222.41,221.63 225.57,224.79 231.44,224.79 v2(231.73,225.09)
  L03_SIGNAL w0.135: 269.56,288.23 269.56,292.56 272.95,295.95 272.95,315.04 285.8,327.89 285.8,359.09 281.63,363.27 263.84,363.27 262.42,364.69 262.42,369.25
  L03_SIGNAL w0.145: 262.42,369.25 262.19,369.49 259.22,369.49 258.77,369.93 258.77,370.47 259.15,370.84 D111.08 ; 269.56,288.23 269.29,287.96 v2(268.83,287.96)
  L22_SIGNAL w0.135: 269.56,287.69 269.56,286.26 267.03,283.73 267.03,274.98 264.34,272.29 264.22,272.17 264.22,246.59 265.04,245.76 270.28,240.53 270.28,214.52 269.27,213.51 260.22,213.51 259.51,214.22 259.51,231.73 258.4,232.85 244.07,232.85 235.94,224.72 232.1,224.72
  L22_SIGNAL w0.145: v2(231.73,225.09) 232.1,224.72 ; v2(268.83,287.96) 269.29,287.96 269.56,287.69
D11109: length 268.7
  TOP w0.203: v2(208.35,240.33) 208.05,240.03 208.05,239.22 205.72,236.89 SITE2.112
  L05_SIGNAL w0.135: 224.25,254.67 224.25,254.1 223.59,253.45 221.34,253.45 219.57,255.22 219.57,305.24 220.81,306.48 220.81,358.29 230.51,368 230.51,377.38 234.04,380.91 252.48,380.91 255.32,378.07 255.32,374.87
  L05_SIGNAL w0.145: 224.25,254.67 224.52,254.94 v2(224.97,254.94) ; D111.09 255.32,374.87
  L22_SIGNAL w0.135: 207.98,240.7 207.98,242.17 208.12,242.3 208.36,242.3 208.5,242.44 208.5,242.71 208.36,242.84 208.12,242.84 207.98,242.97 207.98,243.74 217.8,253.56 217.8,256.58 221.19,259.98 231.97,259.98 233.39,261.39 233.39,266.19 234.07,266.88 236.17,266.88 236.74,266.31 236.74,264.12 240.21,260.65 240.21,257.71 239.79,257.29 233.54,257.29 232.06,255.8 227.2,255.8 225.99,257.02 221.24,257.02 220.61,256.38 220.61,253.86 221.23,253.24 223.51,253.24 224.25,253.98 224.25,254.67
  L22_SIGNAL w0.145: 224.25,254.67 224.52,254.94 v2(224.97,254.94) ; v2(208.35,240.33) 207.98,240.7
D11110: length 268.7
  TOP w0.203: v2(234.78,225.88) 234.48,226.18 225.35,226.18 221.2,222.03 SITE2.85
  L03_SIGNAL w0.135: 252.67,369.24 252.67,361.76 253.88,360.55 280.08,360.55 282.78,357.84 282.78,328.21 269.97,315.4 269.97,299.04
  L03_SIGNAL w0.145: v2(270.69,298.77) 270.24,298.77 269.97,299.04 ; 252.67,369.24 D111.10
  L20_SIGNAL w0.135: 235.15,226.25 238.23,226.25 238.37,226.11 238.37,225.83 238.5,225.7 238.77,225.7 238.9,225.83 238.9,226.11 239.04,226.25 239.31,226.25 239.44,226.11 239.44,225.83 239.58,225.7 239.85,225.7 239.98,225.83 239.98,226.11 240.12,226.25 240.39,226.25 240.52,226.11 240.52,225.83 240.65,225.7 240.92,225.7 241.06,225.83 241.06,226.11 241.19,226.25 276.88,226.25 278.72,228.09 278.72,235.76 273.86,240.62 273.86,243.07 274.83,244.04 274.83,254.54 272.51,256.86 267.79,256.86 264.47,260.18 264.47,283.34 265.48,284.35 275.27,284.35 277.81,286.89 277.81,290.94 274.96,293.8 273.14,293.8 269.97,296.97 269.97,298.5
  L20_SIGNAL w0.145: 269.97,298.5 270.24,298.77 v2(270.69,298.77) ; v2(234.78,225.88) 235.15,226.25
D11111: length 268.7
  TOP w0.203: SITE2.113 205.32,237.26 207.5,239.45 207.5,240.03 v2(207.21,240.33)
  L05_SIGNAL w0.135: 254.91,374.93 254.91,377.9 252.31,380.5 234.21,380.5 230.92,377.21 230.92,367.83 221.22,358.12 221.22,306.31 219.98,305.07 219.98,255.39 221.51,253.86 223.42,253.86 223.84,254.27 223.84,254.67
  L05_SIGNAL w0.145: v2(223.11,254.94) 223.57,254.94 223.84,254.67 ; 254.91,374.93 254.58,374.6 251.34,374.6 251.01,374.27 251.01,373.59 251.22,373.38 D111.11
  L22_SIGNAL w0.135: 207.57,240.7 207.57,243.91 217.39,253.73 217.39,256.75 221.02,260.38 231.8,260.38 232.98,261.56 232.98,266.36 233.9,267.29 236.34,267.29 237.15,266.48 237.15,264.29 240.62,260.82 240.62,257.55 239.96,256.88 233.71,256.88 232.23,255.39 227.03,255.39 225.82,256.61 221.41,256.61 221.01,256.21 221.01,254.03 221.4,253.65 223.34,253.65 223.84,254.15 223.84,254.67
  L22_SIGNAL w0.145: v2(207.21,240.33) 207.57,240.7 ; 223.84,254.67 223.57,254.94 v2(223.11,254.94)
D11112: length 268.7
  TOP w0.203: SITE2.86 220.82,222.43 225.12,226.72 234.48,226.72 v2(234.78,227.02)
  L03_SIGNAL w0.135: 252.26,369.25 252.26,361.59 253.71,360.14 279.91,360.14 282.37,357.67 282.37,328.38 269.56,315.57 269.56,299.04
  L03_SIGNAL w0.145: D111.12 249,370.84 248.63,370.47 248.63,369.88 249.02,369.49 252.03,369.49 252.26,369.25 ; 269.56,299.04 269.29,298.77 v2(268.83,298.77)
  L20_SIGNAL w0.135: 269.56,298.5 269.56,296.8 272.97,293.39 274.79,293.39 277.41,290.78 277.41,287.06 275.1,284.76 265.31,284.76 264.06,283.51 264.06,260.01 267.62,256.46 272.34,256.46 274.42,254.37 274.42,244.21 273.45,243.24 273.45,240.45 278.31,235.59 278.31,228.26 276.71,226.65 235.15,226.65
  L20_SIGNAL w0.145: 269.56,298.5 269.29,298.77 v2(268.83,298.77) ; v2(234.78,227.02) 235.15,226.65
D11113: length 268.7
  TOP w0.203: v2(206.42,243.07) 206.12,242.77 206.12,239.06 204.92,237.85 SITE2.114
  L05_SIGNAL w0.135: 244.69,375.34 244.69,376.59 243,378.28 235.13,378.28 233.14,376.29 233.14,366.91 223.43,357.2 223.43,298.23 224.75,296.91 224.75,271.66 226.07,270.34 226.07,264.47 225.76,264.16 224.77,264.16 224.25,264.68 224.25,265.48
  L05_SIGNAL w0.145: 224.25,265.48 224.52,265.75 v2(224.97,265.75) ; D111.13 244.69,375.34
  L20_SIGNAL w0.135: 224.25,265.48 224.25,264.19 224.45,263.99 225.82,263.99 226.18,264.36 226.18,275.8 227.02,276.63 240.66,276.63 241.5,275.79 241.5,273.95 240.69,273.13 229.16,273.13 228.64,272.61 228.64,271.19 229.1,270.73 240.11,270.73 240.9,269.94 240.9,268.42 240.08,267.6 232.71,267.6 225.03,259.92 215.45,259.92 213.82,258.29 213.82,253.65 206.05,245.88 206.05,245.16 206.19,245.02 206.43,245.02 206.57,244.89 206.57,244.62 206.43,244.48 206.19,244.48 206.05,244.35 206.05,243.43
  L20_SIGNAL w0.145: v2(224.97,265.75) 224.52,265.75 224.25,265.48 ; v2(206.42,243.07) 206.05,243.43
D11114: length 268.7
  TOP w0.203: v2(223.2,243.07) 222.91,242.77 222.91,238.16 220.65,235.9 220.65,233.11 214.92,227.38 SITE2.89
  L03_SIGNAL w0.135: 254.73,299.04 254.73,304.5 279.45,329.22 279.45,356.46 278.34,357.57 246,357.57 242.13,361.44 242.13,368.86
  L03_SIGNAL w0.145: 254.73,299.04 255,298.77 v2(255.45,298.77) ; 242.13,368.86 D111.14
  L20_SIGNAL w0.135: 254.73,298.5 254.73,295.5 259.12,291.11 259.12,256.1 263.33,251.88 268.5,251.88 269.47,250.91 269.47,234.31 268.24,233.08 243.12,233.08 229.45,246.74 225.02,246.74 224.06,245.79 224.06,245.6 224.23,245.42 224.23,245.23 224.04,245.04 223.85,245.04 223.68,245.22 223.49,245.22 222.84,244.57 222.84,243.43
  L20_SIGNAL w0.145: v2(223.2,243.07) 222.84,243.43 ; 254.73,298.5 255,298.77 v2(255.45,298.77)
D11115: length 268.7
  TOP w0.203: v2(205.28,243.07) 205.57,242.77 205.57,239.29 204.52,238.23 SITE2.115
  L05_SIGNAL w0.135: 223.84,265.48 223.84,264.51 224.6,263.75 225.93,263.75 226.48,264.3 226.48,270.51 225.16,271.83 225.16,297.08 223.84,298.4 223.84,357.03 233.55,366.74 233.55,376.12 235.29,377.87 242.83,377.87 244.28,376.42 244.28,375.3
  L05_SIGNAL w0.145: v2(223.11,265.75) 223.57,265.75 223.84,265.48 ; D111.15 242.8,374.61 243.6,374.61 244.28,375.3
  L20_SIGNAL w0.135: 223.84,265.48 223.84,264.02 224.28,263.58 225.99,263.58 226.59,264.19 226.59,275.63 227.19,276.23 240.49,276.23 241.1,275.62 241.1,274.11 240.52,273.54 228.99,273.54 228.23,272.78 228.23,271.02 228.93,270.32 239.94,270.32 240.49,269.77 240.49,268.59 239.91,268.01 232.54,268.01 224.86,260.33 215.28,260.33 213.42,258.46 213.42,253.82 205.64,246.05 205.64,243.43
  L20_SIGNAL w0.145: v2(223.11,265.75) 223.57,265.75 223.84,265.48 ; v2(205.28,243.07) 205.64,243.43
D11116: length 268.7
  TOP w0.203: SITE2.90 214.52,227.76 220.1,233.34 220.1,236.13 222.36,238.39 222.36,242.77 v2(222.06,243.07)
  L03_SIGNAL w0.135: 241.72,368.97 241.72,361.27 245.83,357.16 278.17,357.16 279.04,356.3 279.04,329.39 254.32,304.67 254.32,299.04
  L03_SIGNAL w0.145: D111.16 240.38,369.49 241.21,369.49 241.72,368.97 ; v2(253.59,298.77) 254.05,298.77 254.32,299.04
  L20_SIGNAL w0.135: 222.43,243.43 222.43,244.73 224.85,247.15 229.62,247.15 243.29,233.49 268.07,233.49 269.06,234.48 269.06,250.74 268.33,251.48 263.16,251.48 258.71,255.93 258.71,290.94 254.32,295.33 254.32,298.5
  L20_SIGNAL w0.145: 254.32,298.5 254.05,298.77 v2(253.59,298.77) ; v2(222.06,243.07) 222.43,243.43
D11201: length 231.3
  L07_SIGNAL w0.17: D112.01 270.27,400.56 234.71,400.56 228.62,394.46 228.62,306.07 220.23,297.69 220.23,275.14 213.06,267.97 190.2,267.97 185.06,262.83 v1(185.06,248.48)
D11202: length 189.1
  TOP w0.231: UNK2UT1.2 v1(228.57,244.22)
  L07_SIGNAL w0.17: v1(228.57,244.22) 230.22,245.87 230.22,256.01 229.38,256.86 229.38,271.33 226.33,274.38 226.33,296.24 233.95,303.86 233.95,380.56 237.18,383.79 267.22,383.79 D112.02
D11203: length 230.3
  L07_SIGNAL w0.17: D112.03 265.95,399.8 235.03,399.8 229.38,394.15 229.38,305.75 221,297.37 221,274.83 213.38,267.21 190.52,267.21 186.05,262.74 186.05,244.17 v1(185.06,243.18)
D11204: length 183.4
  TOP w0.231: UNK2UT1.1 v1(228.57,245.49)
  L07_SIGNAL w0.17: v1(228.57,245.49) 229.47,246.39 229.47,255.68 228.62,256.54 228.62,271.02 225.57,274.07 225.57,296.56 233.19,304.18 233.19,380.88 236.87,384.56 262.91,384.56 D112.04
D11205: length 221.5
  L07_SIGNAL w0.17: D112.05 261.64,399.03 235.34,399.03 230.14,393.83 230.14,305.44 221.76,297.06 221.76,273.3 213.38,264.92 213.38,247.4 213.01,247.03 213.01,243.03 210.95,240.97 210.95,228.73 208.82,226.59 208.82,223.18 v1(208.23,222.59)
D11206: length 209.3
  TOP w0.231: v1(215.72,218.46) 216.09,218.83 SITE2.77
  L07_SIGNAL w0.17: v1(215.72,218.46) 215.72,225.82 219.99,230.09 219.99,236.74 224.57,241.32 224.57,252.5 226.33,254.25 226.33,271.78 224.81,273.3 224.81,296.87 232.43,304.49 232.43,381.19 236.55,385.32 258.59,385.32 D112.06
D11207: length 214.7
  L07_SIGNAL w0.17: v1(209.43,222.59) 210.07,223.23 210.07,225.22 213.68,228.83 213.68,237.5 214.91,238.73 214.91,241.28 216.74,243.11 216.74,266.76 223.28,273.3 223.28,297.5 230.9,305.12 230.9,393.51 235.66,398.27 257.32,398.27 D112.07
D11208: length 201.3
  L07_SIGNAL w0.17: D112.08 254.27,386.08 236.24,386.08 231.66,381.51 231.66,304.81 224.04,297.19 224.04,272.54 221.76,270.26 221.76,260.04 220.69,258.98 220.69,243.09 218.8,241.19 218.8,231.32 213.48,226 v1(213.48,219.47)
D11209: length 268.7
  TOP w0.203: v2(177.25,221.18) 177.55,220.88 187.27,220.88 188.52,219.63 SITE2.142
  L05_SIGNAL w0.135: 255.54,394.96 255.54,396.84 251.02,401.37 233.1,401.37 211.34,379.6 211.34,320.37 190.8,299.83 190.8,265.45 191.83,264.42 192.99,264.42 193.5,264.93 193.5,265.48
  L05_SIGNAL w0.145: 193.5,265.48 193.77,265.75 v2(194.23,265.75) ; D112.09 255.54,394.96
  L20_SIGNAL w0.135: 193.5,265.48 193.5,264.93 192.2,263.63 190.34,263.63 181.66,254.94 178.82,254.94 170.47,246.59 170.47,223.85 173.5,220.81 174,220.81 174.13,220.95 174.13,221.18 174.27,221.32 174.54,221.32 174.67,221.18 174.67,220.95 174.81,220.81 175.08,220.81 175.21,220.95 175.21,221.18 175.35,221.32 175.61,221.32 175.75,221.18 175.75,220.95 175.88,220.81 176.88,220.81
  L20_SIGNAL w0.145: v2(177.25,221.18) 176.88,220.81 ; v2(194.23,265.75) 193.77,265.75 193.5,265.48
D11210: length 268.7
  TOP w0.203: v2(192.91,240.33) 192.62,240.03 192.62,233.23 198.12,227.73 SITE2.131
  L03_SIGNAL w0.135: 252.25,389.14 252.25,386.83 244.37,378.95 236.17,378.95 233.92,376.7 233.92,350.89 223.1,340.07 223.1,326.77 197.32,300.99 197.32,295.45 193.5,291.64 193.5,288.23
  L03_SIGNAL w0.145: 252.25,389.14 D112.10 ; v2(194.23,287.96) 193.77,287.96 193.5,288.23
  L22_SIGNAL w0.135: 192.55,240.7 192.55,241.82 192.68,241.95 192.93,241.95 193.06,242.09 193.06,242.36 192.93,242.49 192.68,242.49 192.55,242.62 192.55,247.07 201.47,256 201.47,266.75 206.23,271.5 206.23,311.14 204.16,313.21 197.43,313.21 195.88,311.66 195.88,287.06 195.25,286.44 193.77,286.44 193.5,286.71 193.5,287.69
  L22_SIGNAL w0.145: v2(194.23,287.96) 193.77,287.96 193.5,287.69 ; v2(192.91,240.33) 192.55,240.7
D11211: length 268.7
  TOP w0.203: v2(177.25,220.04) 177.55,220.33 187.04,220.33 188.15,219.23 SITE2.143
  L05_SIGNAL w0.135: 255.14,395.15 255.14,396.67 250.85,400.96 233.27,400.96 211.75,379.43 211.75,320.2 191.21,299.66 191.21,265.62 192,264.83 192.83,264.83 193.09,265.1 193.09,265.48
  L05_SIGNAL w0.145: 255.14,395.15 254.86,394.87 251.6,394.87 251.17,394.44 251.17,393.89 251.35,393.7 D112.11 ; 193.09,265.48 192.83,265.75 v2(192.37,265.75)
  L20_SIGNAL w0.135: 193.09,265.48 193.09,265.1 192.03,264.04 190.17,264.04 181.49,255.35 178.65,255.35 170.06,246.76 170.06,223.68 173.33,220.4 176.88,220.4
  L20_SIGNAL w0.145: 193.09,265.48 192.83,265.75 v2(192.37,265.75) ; v2(177.25,220.04) 176.88,220.4
D11212: length 268.7
  TOP w0.203: SITE2.132 197.72,227.35 192.07,233 192.07,240.03 v2(191.77,240.33)
  L03_SIGNAL w0.135: 251.84,389.19 251.84,386.99 244.2,379.36 236,379.36 233.51,376.87 233.51,351.06 222.69,340.24 222.69,326.94 196.91,301.15 196.91,295.62 193.09,291.81 193.09,288.23
  L03_SIGNAL w0.145: D112.12 250.37,389.98 251.05,389.98 251.84,389.19 ; 193.09,288.23 192.83,287.96 v2(192.37,287.96)
  L22_SIGNAL w0.135: 193.09,287.69 193.09,286.54 193.6,286.03 195.42,286.03 196.29,286.89 196.29,311.49 197.6,312.8 203.99,312.8 205.82,310.97 205.82,271.67 201.06,266.92 201.06,256.17 192.14,247.24 192.14,240.7
  L22_SIGNAL w0.145: v2(191.77,240.33) 192.14,240.7 ; 193.09,287.69 192.83,287.96 v2(192.37,287.96)
D11213: length 268.7
  TOP w0.203: v2(180.55,223.11) 180.84,222.81 187.29,222.81 189.67,220.43 SITE2.140
  L05_SIGNAL w0.135: 193.5,254.67 193.5,253.99 193.77,253.72 194.98,253.72 197.18,255.92 197.18,301.9 213.74,318.46 213.74,378.61 234.29,399.16 242.86,399.16 244.71,397.31 244.71,395.64
  L05_SIGNAL w0.145: D112.13 244.71,395.64 ; v2(194.23,254.94) 193.77,254.94 193.5,254.67
  L22_SIGNAL w0.135: 193.5,254.67 193.5,254.12 192.15,252.76 184.56,252.76 181.73,249.94 181.73,240.98 175.11,234.35 175.11,227.45 175.24,227.31 175.48,227.31 175.61,227.18 175.61,226.91 175.48,226.78 175.24,226.78 175.11,226.64 175.11,226.37 175.24,226.24 175.48,226.24 175.61,226.1 175.61,225.83 175.48,225.7 175.24,225.7 175.11,225.56 175.11,214.06 175.91,213.26 180.3,213.26 180.87,213.83 180.87,217.77 178.58,220.06 178.58,222.2 179.13,222.74 180.18,222.74
  L22_SIGNAL w0.145: v2(194.23,254.94) 193.77,254.94 193.5,254.67 ; v2(180.55,223.11) 180.18,222.74
